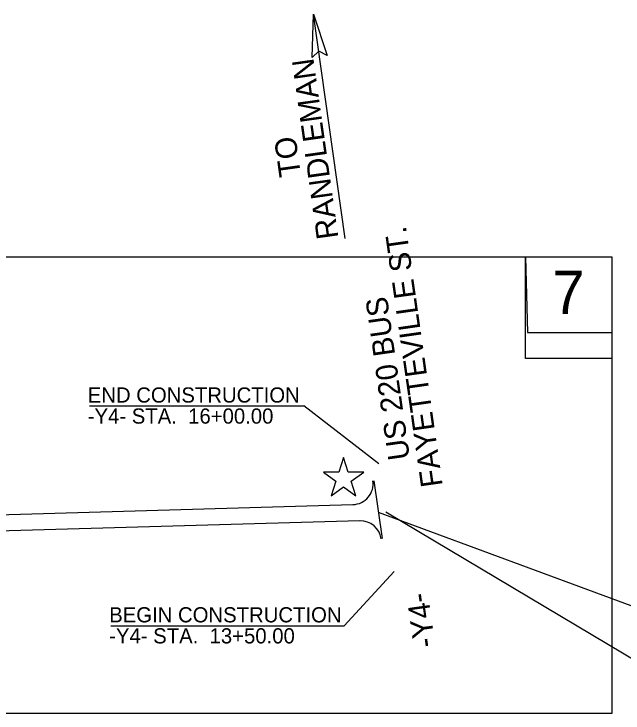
# Model space of a CAD drawing. Extents: x 1750553 to 1763838, y 734059 to 742526.
# Drawn here: x 1759426 to 1760830, y 736593 to 738204 of the extents above; entities that cross this region are included whole.
import ezdxf

# ---------------------------------------------------------------- set-up
doc = ezdxf.new("R2010")
doc.units = 0
for name, color, linetype in [('ENG SEALS CELL', 7, 'Continuous'), ('Old_Level_2', 7, 'Continuous'), ('Prop Horizontal Alignment', 7, 'Continuous'), ('Prop RDY Traffic Signal CELL', 7, 'Continuous'), ('Prop Terminator CELL', 7, 'Continuous'), ('Sheet PE Seal Cell', 7, 'Continuous')]:
    doc.layers.add(name, color=color, linetype=linetype)

msp = doc.modelspace()

# ---------------------------------------------------------------- linework, layer by layer
at = {"layer": 'ENG SEALS CELL'}
msp.add_lwpolyline([(1759365.7, 737643), (1759395.5, 736593), (1760805, 736593), (1760805, 737409.8), (1760605, 737409.8), (1760605, 737643)], close=True, dxfattribs=at)
at = {"layer": 'Old_Level_2'}
for p, q in [((1760255.3, 737128.2), (1760274.3, 736994.7)), ((1759002.6, 737039), (1760207.2, 737073.2)), ((1760223.4, 737035.7), (1757498.7, 736958.3))]:
    msp.add_line(p, q, dxfattribs=at)
for centre, start, end in [((1760205.8, 737121.2), 271.6265, 8.09), ((1760224.8, 736987.7), 8.09, 91.6265)]:
    msp.add_arc(centre, 48, start, end, dxfattribs=at)
at = {"layer": 'Prop Horizontal Alignment'}
msp.add_line((1760265.6, 737055.9), (1760904.4, 736819.6), dxfattribs=at)
at = {"layer": 'Prop RDY Traffic Signal CELL'}
msp.add_lwpolyline([(1760174.6, 737147.6), (1760139.2, 737147.6), (1760167.8, 737126.9), (1760156.9, 737093.2), (1760185.5, 737114), (1760214.2, 737093.2), (1760203.2, 737126.9), (1760231.9, 737147.7), (1760196.5, 737147.7), (1760185.5, 737181.4), (1760174.6, 737147.6)], dxfattribs=at)
at = {"layer": 'Prop Terminator CELL'}
msp.add_lwpolyline([(1760113.4, 738103.5), (1760116.5, 738203.5), (1760147.7, 738107.7), (1760128.6, 738117.8)], close=True, dxfattribs=at)
at = {"layer": 'Sheet PE Seal Cell'}
for p, q in [((1760189, 737686.1), (1760116.5, 738203.5)), ((1759599.8, 737300.8), (1760094.1, 737300.8)), ((1760267, 737166.9), (1760094.1, 737300.8)), ((1760282.7, 737056.4), (1761035.9, 736608.2)), ((1760302.2, 736919.4), (1760186.7, 736793.7)), ((1759648.9, 736793.7), (1760186.7, 736793.7))]:
    msp.add_line(p, q, dxfattribs=at)
for points in [[(1759365.7, 737643), (1759395.5, 736593), (1760805, 736593), (1760805, 737643)], [(1760805, 737643), (1760605, 737643), (1760609.9, 737469.4), (1760609.9, 737469.4), (1760805, 737469.4)]]:
    msp.add_lwpolyline(points, close=True, dxfattribs=at)

# ---------------------------------------------------------------- texts
for s, height, rotation, p in [('RANDLEMAN', 50, 97.9681, (1760173.9, 737688.1)), ('TO ', 50, 97.9681, (1760087.5, 737832)), ('FAYETTEVILLE ST.', 50, 98.09, (1760414.3, 737117)), ('US 220 BUS', 50, 98.09, (1760338.7, 737179.2)), ('END CONSTRUCTION', 35, 360, (1759595.8, 737308.2)), ('-Y4- STA.  16+00.00', 35, 360, (1759595.8, 737259.7)), ('-Y4-', 50, 97.9681, (1760397.3, 736747.1)), ('BEGIN CONSTRUCTION', 35, 360, (1759645.2, 736801.8)), ('-Y4- STA.  13+50.00', 35, 360, (1759645.2, 736753.3))]:
    msp.add_text(s, height=height, rotation=rotation, dxfattribs=at).set_placement(p)
msp.add_text('7', height=100, dxfattribs=at).set_placement((1760666.6, 737512.2))

doc.saveas('drawing.dxf')
